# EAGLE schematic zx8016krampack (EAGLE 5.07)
D2: D2'
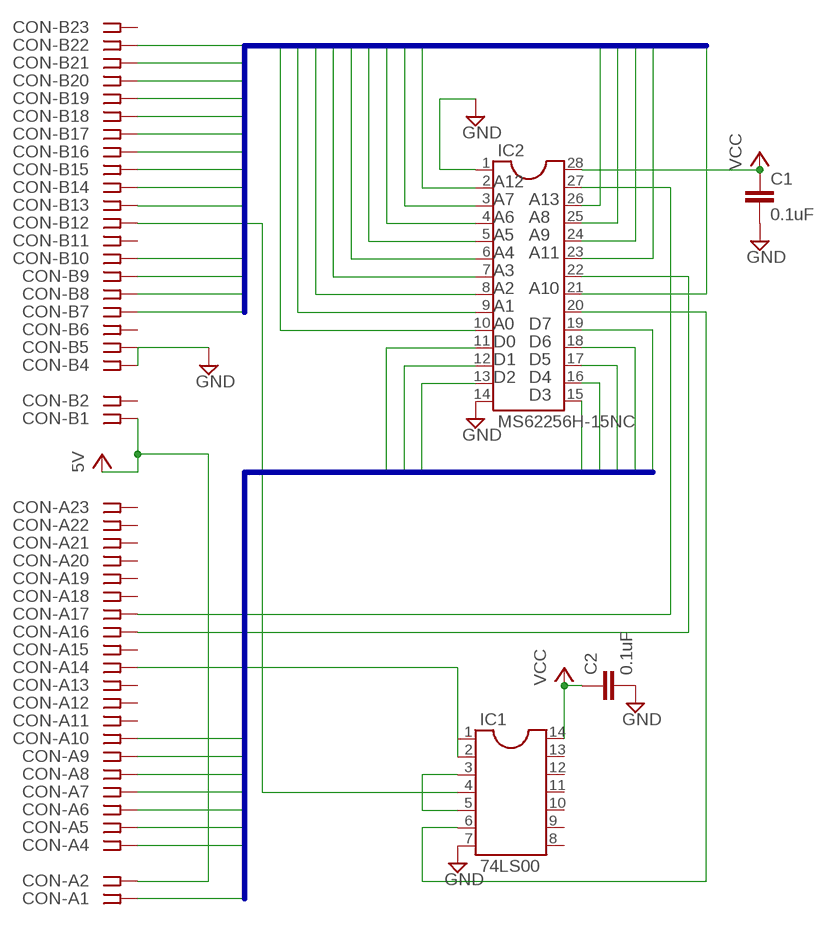
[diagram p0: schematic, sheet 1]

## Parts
C1  0.1uF  C5/2.5  [C5B2.5]
C2  0.1uF  C5/2.5  [C5B2.5]
CON  ISA-SLOT  [ISA-16]
IC1  74LS00  DIL14  [DIL14]
IC2  MS62256H-15NC  DIL28-3  [DIL28-3]

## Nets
A0: CON.B7 IC2.10
A1: CON.B8 IC2.9
A2: CON.B9 IC2.8
A3: CON.B10 IC2.7
A4: CON.B22 IC2.6
A5: CON.B21 IC2.5
A6: CON.B20 IC2.4
A7: CON.B19 IC2.3
A8: CON.B18 IC2.25
A9: CON.B17 IC2.24
A10: CON.B16 IC2.21
A11: CON.B15 IC2.23
A12: CON.B14 IC2.2
A13: IC2.26
D0: CON.A4 IC2.11
D1: CON.A5 IC2.12
D2: CON.A6 IC2.13
D3: CON.A9 IC2.15
D4: CON.A10 IC2.16
D5: CON.A8 IC2.17
D6: CON.A7 IC2.18
D7: CON.A1 IC2.19
GND: C1.2 C2.2 CON.B4 CON.B5 IC1.7 IC2.1 IC2.14
N$1: CON.A14 IC1.1 IC1.2
N$2: IC1.3 IC1.5
N$3: IC1.6 IC2.20
N$4: CON.A16 IC2.22
N$5: CON.A17 IC2.27
N$6: CON.B12 IC1.4
N$7: CON.B13
VCC: C1.1 C2.1 CON.A2 CON.B1 IC1.14 IC2.28 ; supply symbol labelled 5V
Unconnected: CON.A3 CON.A11 CON.A12 CON.A13 CON.A15 CON.A18 CON.A19 CON.A20 CON.A21 CON.A22 CON.A23 CON.A24 CON.A25 CON.A26 CON.A27 CON.A28 CON.A29 CON.A30 CON.A31 CON.B2 CON.B3 CON.B6 CON.B11 CON.B23 CON.B24 CON.B25 CON.B26 CON.B27 CON.B28 CON.B29 CON.B30 CON.B31 CON.C1 CON.C2 CON.C3 CON.C4 CON.C5 CON.C6 CON.C7 CON.C8 CON.C9 CON.C10 CON.C11 CON.C12 CON.C13 CON.C14 CON.C15 CON.C16 CON.C17 CON.C18 CON.D1 CON.D2 CON.D3 CON.D4 CON.D5 CON.D6 CON.D7 CON.D8 CON.D9 CON.D10 CON.D11 CON.D12 CON.D13 CON.D14 CON.D15 CON.D16 CON.D17 CON.D18 IC1.8 IC1.9 IC1.10 IC1.11 IC1.12 IC1.13

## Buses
D[0..7]
A[0..13]

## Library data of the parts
C1 C2 = capacitor-wima:C: CAPACITOR
CON = con-pc:ISA-SLOT: ISA SLOT
IC1 = ic-package:DIL14: Dual In Line / Socket
IC2 = ic-package:DIL28: Dual In Line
